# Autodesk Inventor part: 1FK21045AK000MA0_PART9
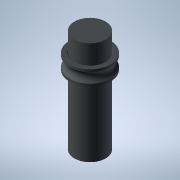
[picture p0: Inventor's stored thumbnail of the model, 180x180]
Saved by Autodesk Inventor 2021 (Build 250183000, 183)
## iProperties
Created: 2025-04
Part Number: 1FK21045AK000MA0_PART9
Material: Generic
Catalog Web Link: www.3dfindit.com
Description: -Servo synchronous motor
Document SubType Name: Modeling
Designer: psAdmin
Mass: 18.6788 g
Surface Area: 52.316 cm^2
Volume: 18.6788 cm^3
Density: 1 g/cm^3
Appearance: PSOLRGB-212-217-219
Category: PARTsolutions
Title: 1FK21045AK000MA0_PART9
Author: Cadenas PARTsolutions
Comments: Servo synchronous motor
Sending System: PARTsolutions
Preprocessor: ST-DEVELOPER v19.3
PSOL_IDENT_0: {$CADENAS_DATA/23d-libs/siemens_ag/_cat_/3d/2f/1fk21045ak000ma0.prj},213 {VTYP=3D},{NB=1FK21045AK000
PSOL_IDENT_1: MA0_PART9},{LINA=1FK21045AK000MA0_PART9},{NN=1FK21045AK000MA0_PART9},{NOPRJ=TRUE},{DATE=19.08.2025 1
PSOL_IDENT_2: 4:00:34},{GEOMDATE=30.07.2025 02:01:24},{VERSION=},{LINEID=10},{WBVAR=},{WBNUMERIC=}  {NB=1FK21045AK
PSOL_IDENT_3: 000MA0_PART9},{LINA=1FK21045AK000MA0_PART9},{KT=DUMMY},{PREVIEW=../../../_pool_/a9/69/p_d211_xx_0081
PSOL_IDENT_4: 8j.png},{DESCSHORT=SIMOTICS S-1FK2 HD, SINAMICS S210 3AC 400V-480V, 1.7 Nm, 6000 rpm},{DESCLONG=SIMO
PSOL_IDENT_5: TICS S-1FK2 HD servo motor M0=2.4 Nm; PN = 1.07 kW at nN=6000 rpm (380-480 V); PN = 0.75 kW at nN=30
PSOL_IDENT_6: 00 rpm (200-240 V); degree of protection IP64; cylindrical shaft D19x40mm; absolute encoder 22-bit +
PSOL_IDENT_7: 12-bit multiturn (encoder AM22DQC); with OCC interface; plug size M17, rotatable; SIMOTICS S-1FK2 s
PSOL_IDENT_8: ervomotorfor a wide range of uses in industrial environments. SIMOTICS S‑1FK2 servomotors are compac
PSOL_IDENT_9: t synchronous motors with a high dynamic performance that set themselves apart as a result of their
PSOL_IDENT_10: high power density, degree of protection and overload capability. The motors are available in two va
PSOL_IDENT_11: riants: as High Dynamic variant (highest dynamic performance as a result of the low intrinsic moment
PSOL_IDENT_12: of inertia for applications demanding a high dynamic performance with low moved masses) - and as Co
PSOL_IDENT_13: mpact variant (precise and stable closed-loop control for medium up to large moved masses as a resul
PSOL_IDENT_14: t of a medium intrinsic moment of inertia). SIMOTICSS‑1FK2 servomotors fully exploit their strengths
PSOL_IDENT_15: in a system with the SINAMICSS210 frequency converter and simple connection using the one cable con
PSOL_IDENT_16: nection (OCC). Advantages include the short control and positioning times, fast and precise correcti
PSOL_IDENT_17: on of disturbing quantities as well as stable control with a high dynamic performance. The servo mot
PSOL_IDENT_18: ors can be configured to address a wide range of requirements. For example with and without holding
PSOL_IDENT_19: brake, IP64 or IP65 degree of protection, singleturn or multiturn absolute encoders - to name just a
PSOL_IDENT_20: few. Further, the servomotors are available in different shaft heights extending from 20 to 100. A
PSOL_IDENT_21: shaft sealing ring is available to achieve an IP65 degree of protection and for subsequent mounting
PSOL_IDENT_22: at the motor or as spare part. SIMOTICS - the optimum motor for each and every motion control applic
PSOL_IDENT_23: ation.},{INTNO=804766789342},{SUPPLIERALTNO=1FK2104-5AK00-0MA0},{MANUID=1FK21045AK000MA0},{MANUNAME=
PSOL_IDENT_24: Siemens},{MANUTYPEDESC=Synchronous motor 1FK2-HD 2,39 Nm},{AAU732=SIMOTICS},{AAO057=S-1FK2},{AAU734=
PSOL_IDENT_25: SIMOTICS S-1FK2 HD servo motor M0=2.4 Nm; PN = 1.07 kW at nN=6000 rpm (380-480 V); PN = 0.75 kW at n
PSOL_IDENT_26: N=3000 rpm (200-240 V); degree of protection IP64; cylindrical shaft D19x40mm; absolute encoder 22-b
PSOL_IDENT_27: it + 12-bit multiturn (encoder AM22DQC); with OCC interface; plug size M17, rotatable;},{AAW338=Sync
PSOL_IDENT_28: hronous motor 1FK2-HD 2,39 Nm},{AAO742=SIMOTICS},{AAO663=4042948691151},{NOCUPEROU=1},{PRICEQUANTITY=
PSOL_IDENT_29: 1},{QUANTITYMIN=1},{QUANTITYINT=1},{CTN=85015100},{COO=DE},{AAO676=1FK2104-5AK00-0MA0},{AAO677=Sieme
PSOL_IDENT_30: ns AG},{ORDERUNIT=C62},{CONTENTUNIT=C62}
NB: 1FK21045AK000MA0_PART9
NT: Servo synchronous motor
NBSYN: $MANUID._PART9
LINA: 1FK21045AK000MA0_PART9
CATALOG: SIEMENS
PREVIEW: ../../../_pool_/a9/69/p_d211_xx_00818j.png
DESCSHORT: SIMOTICS S-1FK2 HD, SINAMICS S210 3AC 400V-480V, 1.7 Nm, 6000 rpm
DESCLONG: SIMOTICS S-1FK2 HD servo motor M0=2.4 Nm; PN = 1.07 kW at nN=6000 rpm (380-480 V); PN = 0.75 kW at nN=3000 rpm (200-240 V); degree of protection IP64; cylindric
INTNO: 804766789342
SUPPLIERALTNO: 1FK2104-5AK00-0MA0
MANUID: 1FK21045AK000MA0
MANUNAME: Siemens
MANUTYPEDESC: Synchronous motor 1FK2-HD 2,39 Nm
AAU732: SIMOTICS
AAO057: S-1FK2
AAU734: SIMOTICS S-1FK2 HD servo motor M0=2.4 Nm; PN = 1.07 kW at nN=6000 rpm (380-480 V); PN = 0.75 kW at nN=3000 rpm (200-240 V); degree of protection IP64; cylindric
AAW338: Synchronous motor 1FK2-HD 2,39 Nm
AAO742: SIMOTICS
AAO663: 4042948691151.0
NOCUPEROU: 1
PRICEQUANTITY: 1
QUANTITYMIN: 1
QUANTITYINT: 1
CTN: 85015100
COO: DE
ARTICLENO: 1FK21045AK000MA0_PART9
BOMINFO: 1FK21045AK000MA0_PART9
CREATOR: CADENAS GmbH
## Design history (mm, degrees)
feature "2025_04_17_15_39_51_0728"
body "Solid1"
